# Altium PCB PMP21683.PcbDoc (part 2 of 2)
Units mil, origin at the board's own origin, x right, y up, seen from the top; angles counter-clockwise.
Board outline 4950 x 3450 mil, 2 copper layers (Top Layer, Bottom Layer), stack 62 mil thick; 134 components, 57 nets, 365 pads, 111 vias.
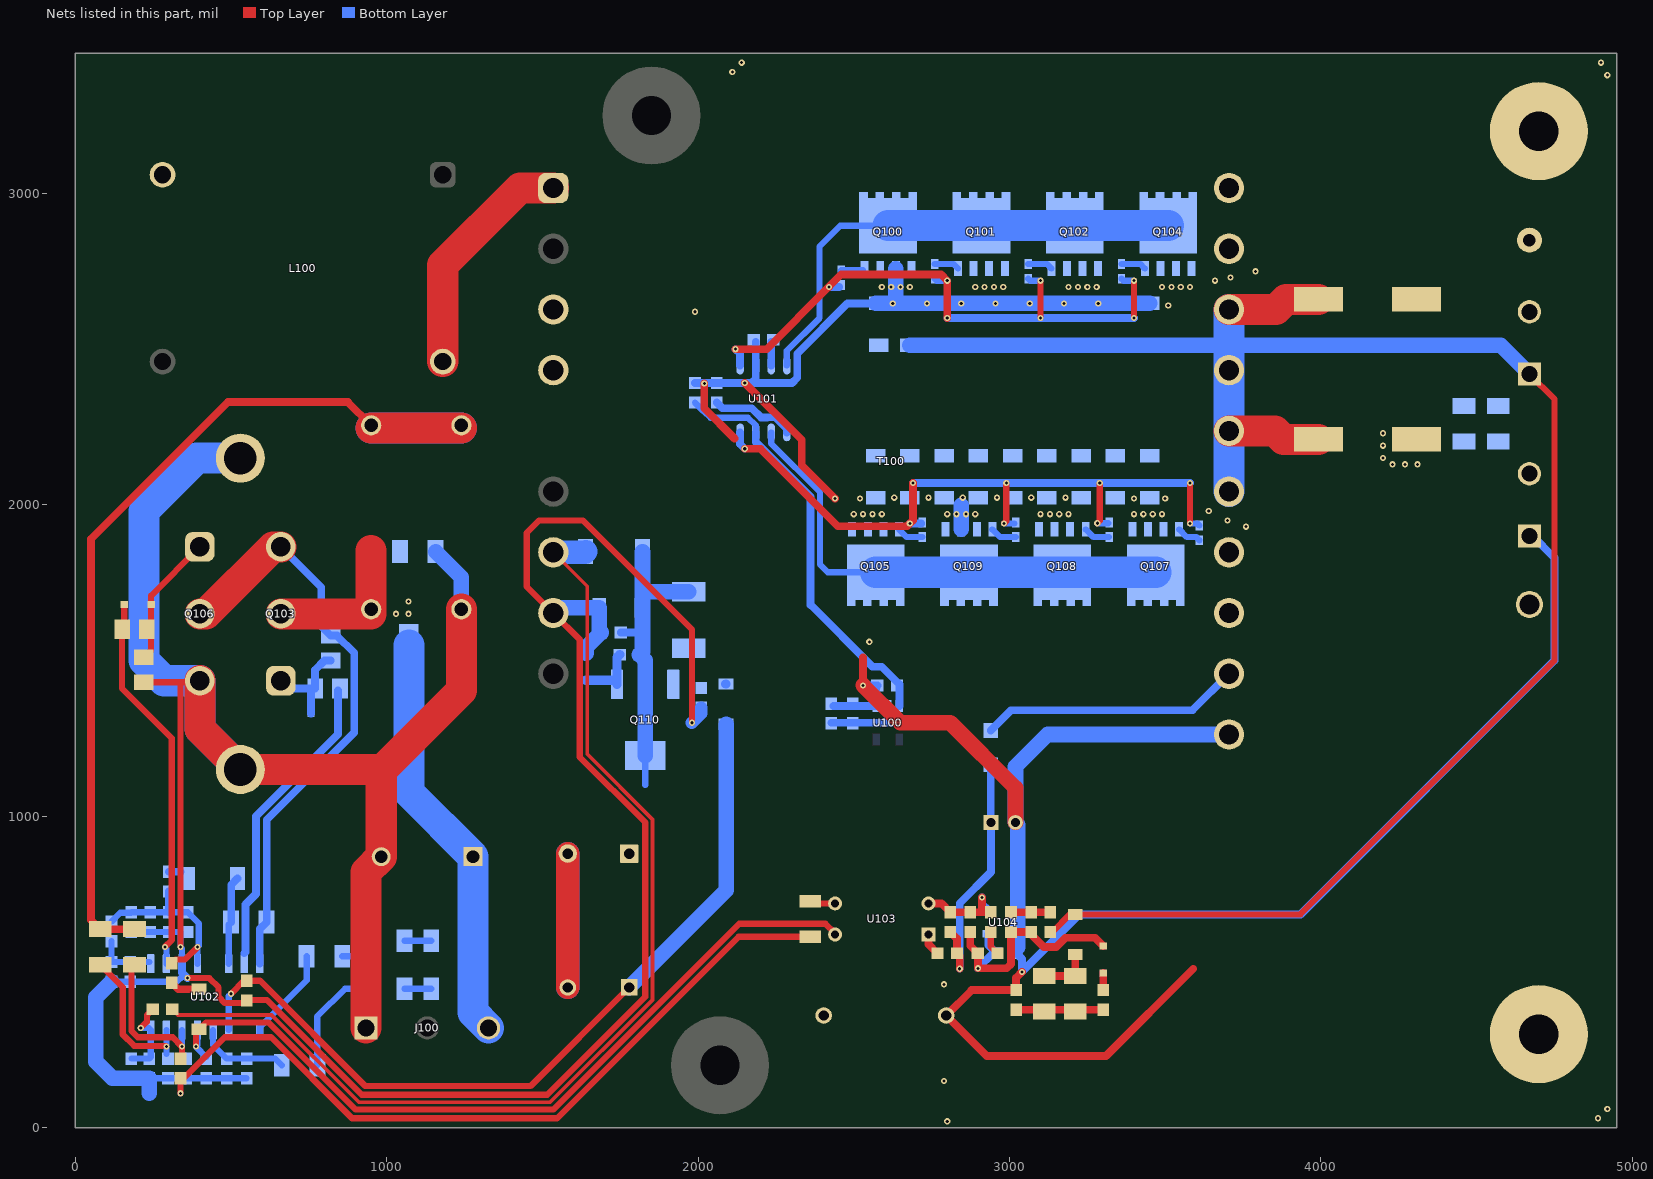
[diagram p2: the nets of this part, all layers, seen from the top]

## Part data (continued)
R136: "RES, 412 k, 1%, 0.1 W, 0603", MANUFACTURER=Vishay-Dale, Power_W=0.1, Supplier Part Number 1=541-412KHCT-ND, TempCo="100 ppm/C", Tolerance_%=1, Value1=1%, Value2=0.1W, Value_Code=412k
R137: "RES, 68.1, 1%, 0.1 W, 0603", MANUFACTURER=Vishay-Dale, Power_W=0.1, Supplier Part Number 1=541-68.1HCT-ND, TempCo="100 ppm/C", Tolerance_%=1, Value1=1%, Value2=0.1W, Value_Code=68R1, ValueDisplayed=68.1
R138: "RES, 57.6 k, 1%, 0.1 W, 0603", MANUFACTURER=Vishay-Dale, Power_W=0.1, Supplier Part Number 1=541-57.6KHCT-ND, TempCo="100 ppm/C", Tolerance_%=1, Value1=1%, Value2=0.1W, Value_Code=57k6, ValueDisplayed=57.6k
T100: library part CMP-0084748-1, "Transformer, 250 uH, TH", MANUFACTURER="Renco Electronics", ValueDisplayed=250µH
TP100: "Test Point, Miniature, Red, TH", Color=Red, MANUFACTURER=Keystone, Supplier Part Number 1=36-5000-ND
TP101: "Test Point, Multipurpose, Black, TH", Color=Black, MANUFACTURER=Keystone, Supplier Part Number 1=36-5011-ND
U100: library part CMP-0035558-1, "Single Output LDO, 150 mA, Fixed 5 V Output, 2.5 to 24 V Input, with Ultra-Low IQ, 5-pin SOT-23 (DBV), -40 to 125 degC, Green (RoHS & no Sb/Br)", MANUFACTURER="Texas Instruments"
U101: library part CMP-0079610-1, "High Performance Synchronous Rectifier Driver for LLC Resonant Converter, D0008A (SOIC-8)", Alternate Manufacturer="Texas Instruments"
U102: library part UCC25630DDB, "Enhanced LLC Resonant Controller with Driver, DDB0014A", Alternate Manufacturer="Texas Instruments"
U103: library part VO618A, "OPTOISOLATOR 5.3KV TRANS 4-DIP", MANUFACTURER=Vishay-Semiconductor, Voltage_Isolation_Vrms=5300V
U104: "Low-Voltage Adjustable Precision Shunt Regulator, 80 mA, -40 to 125 degC, 3-pin SOT-23 (DBZ), Green (RoHS & no Sb/Br)", Alternate Manufacturer="Texas Instruments", Alternate PartNumber=Equivalent, Rating=Catalog, Supplier Part Number 1=296-17972-2-ND, Temp Coeff(Max)(ppm/ degree C)=129

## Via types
v1: diameter 20, hole 10, Top Layer to Bottom Layer, 111 vias

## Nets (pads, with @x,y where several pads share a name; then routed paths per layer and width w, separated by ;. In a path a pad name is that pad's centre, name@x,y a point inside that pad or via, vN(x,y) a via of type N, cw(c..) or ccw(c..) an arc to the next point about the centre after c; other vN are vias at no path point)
5Vs: C106.1 C135.1 U100.3 U101.7 | length 1334.9
  Bottom Layer w20: C135.1@1990,2328.5 2017.13,2301.38 2018.62,2301.38 2040,2280 2160,2280 2185,2255 U101.7@2185,2232.72
  Bottom Layer w25: U101.7@2185,2232.72 2185,2202.04 2361.38,2025.67 2361.38,1678.62 2560,1480 2590,1480 2646.46,1423.54 U100.3@2646.46,1354.29
BLK: C154.1 R129.1 R138.2 U102.4 | length 296
  Bottom Layer w20: U102.4@442.5,313.7 442.5,265.04 C154.1@486.04,221.5 R138.2@550,221.5 641.42,221.5 R129.1@662.91,200
FB: C145.1 D107.2 U102.5 U103.4 | length 2594.1
  Top Layer w20: v1(387.5,260) 387.5,305.53 D107.2@397.5,315.53 419.84,337.87 620,337.87 900,57.87 1535.4,57.87 2132.24,654.71 2408.75,654.71 2440,623.46 U103.4@2440,620
  Bottom Layer w20: U102.5@392.5,313.7 392.5,265 v1(387.5,260) C145.1@420.93,226.57
GND: C100.2 C102.2 C103.2 C107.2 C131.2 C132.1 C133.2 C141.2 C142.2 C143.1 C144.1 C145.2 C146.2 C147.2 C148.2 C149.2 C150.2 C151.2 C152.2 C153.2 C154.2 D109.2 H100.1 H100.2 J100.1 Q106.3 R112.1 R113.1 R135.1 R136.1 R137.1 R138.1 T100.8 U102.11 | length 14543.6
  Top Layer w20: R113.1@220,1430 340,1430 ; v1(337.5,110) R137.1@337.5,158.5 348.5,158.5 480,290 628.45,290 888.45,30 1546.95,30 2130.06,613.11 R135.1@2360,613.11 ; v1(337.5,580) 337.5,1427.5 340,1430 ; v1(360,480) 360.35,480.35 428.92,480.35 429.27,480 430,480 460,450 460,420 480,400 541.5,400 C144.1@550,408.5 551.5,410 615.4,410 919.78,105.62 1515.62,105.62 1830,420 1830,980 1620,1190 1620,1567.5 T100.8@1535,1652.5 1450,1737.5 1450,1910 1490,1950 1630,1950 1980,1600 v1(1980,1300) ; Q106.3@395,1430 340,1430
  Top Layer w75: C141.2@1581.57,450 C142.2@1581.57,880
  Top Layer w100: Q106.3@400,1435 400,1280 H100.2@530,1150 986.54,1150 1240,1403.46 C131.2@1240,1664.72 ; J100.1@933.15,320 933.15,820.79 C100.2@982.36,870 982.36,1145.83
  Bottom Layer w20: R136.1@116.04,468.5 C151.2@176.04,468.5 ; C151.2@177.5,467.05 C151.2@176.04,468.5 ; C147.2@180,628.5 C148.2@240,628.5 C150.2@300,628.5 337.5,628.5 v1(337.5,580) 342.5,575 U102.11@342.5,526.3 ; C153.2@237.5,158.5 C152.2@297.5,158.5 C146.2@356.18,158.5 C145.2@420.93,158.5 C154.2@486.04,158.5 R138.1@550,158.5 ; U102.11@342.5,497.5 342.5,485 326,468.5 C151.2@176.04,468.5
  Bottom Layer w25: U102.11@342.5,526.3 342.5,497.5 v1(360,480)
  Bottom Layer w39.37: v1(1980,1300) 2010,1330 C143.1@2010,1348.5
  Bottom Layer w50: R136.1@116.04,468.5 65.96,418.43 65.96,211.54 119,158.5 C153.2@237.5,158.5 237.5,110 ; C102.2@1157.09,1850 1240,1767.09 C131.2@1240,1664.72 1228.74,1653.46 C103.2@1228.74,1550 ; T100.8@1552.5,1670 C133.2@1683.07,1670 1683.07,1595.43 C132.1@1688.5,1590 1640,1541.5 D109.2@1640,1523.31
  Bottom Layer w75: C141.2@1581.57,450 C142.2@1581.57,880
  Bottom Layer w100: H100.2@530,1150 400,1280 Q106.3@400,1435 285,1435 220,1500 220,1980 390,2150 H100.1@530,2150
HO: D101.1 R105.1 U102.15 | length 967.9
  Bottom Layer w25: 542.5,560 546.38,563.88 546.38,716.38 580,750 580,1000.12 843.31,1263.42 D101.1@843.31,1330 R105.1@843.31,1403.31
HS: C136.2 L100.2 Q103.3 Q106.2 R104.1 U102.16 | length 1922.4
  Top Layer w100: Q106.2@400,1650 420,1650 635,1865 Q103.3@660,1865
  Bottom Layer w25: U102.16@592.5,526.3 592.5,637.91 C136.2@614.59,660 614.59,988.21 895.37,1269 895.37,1524.63 840,1580 R104.1@820,1580 790,1610 790,1735 Q103.3@660,1865
ISNS: C129.2 C146.1 R137.2 U102.6 | length 506.5
  Top Layer w20: C129.2@180,512.91 180,310.58 200.58,290 312.5,290 v1(342.5,260) R137.2@342.5,226.5
  Bottom Layer w20: C146.1@342.5,226.5 v1(342.5,260) U102.6@342.5,313.7
LO: D103.1 R114.1 U102.10 | length 1233.8
  Top Layer w20: D103.1@156.69,1680 156.69,1606.69 R114.1@150,1600 150,1410 309.63,1250.37 309.63,602.13 v1(287.5,580)
  Bottom Layer w20: v1(287.5,580) 292.5,575 U102.10@292.5,526.3
NetC108_2: C108.2 C129.1 C130.1 C131.1 T100.3 T100.4 | length 3068.5
  Top Layer w25: C129.1@190,637.09 C130.1@80,637.09 50,667.09 50,1890 490,2330 875.28,2330 C108.2@950,2255.28
  Top Layer w100: C108.2@950,2246.85 C131.1@1240,2246.85
  Bottom Layer w100: C108.2@950,2246.85 C131.1@1240,2246.85
NetC134_2: C134.2 U101.3 | length 76.2
  Bottom Layer w25: U101.3@2235,2447.28 C134.2@2235,2523.5
NetC136_1: C136.1 D104.1 U102.14 | length 274
  Bottom Layer w20: U102.14@492.5,526.3 C136.1@492.5,652.09
  Bottom Layer w25: C136.1@500.41,660 500.41,780.1 D104.1@520.32,800
NetC137_1: C137.1 C139.2 R127.1 U103.2 U104.2 | length 308.8
  Top Layer w25: U103.2@2740,720 2781.5,720 R127.1@2810,691.5 C137.1@2874.21,691.5 2911.46,691.5 ; v1(2911.46,738.54) 2911.46,691.5 ; C139.2@2940,691.5 2911.46,691.5
  Bottom Layer w25: v1(2911.46,738.54) 2911.46,718.7 U104.2@2932.76,697.4
NetC137_2: C137.2 C138.1 D108.1 R128.1 R131.2 R139.2 U104.1 | length 829.4
  Top Layer w25: C137.2@2874.21,628.5 2874.21,584.29 R131.2@2898.5,560 v1(2898.5,511.5) 2991.5,511.5 3005,525 R128.1@3005,628.5 C138.1@3070,628.5 3070,620 3110,580 3150,580 3180,610 3274.61,610 D108.1@3301.3,583.31
  Bottom Layer w25: v1(2898.5,511.5) R139.2@2947.01,560 ; U104.1@2932.76,622.6 2932.76,585.73 R139.2@2958.49,560
NetC138_2: C138.2 R118.2 R128.2 | length 126.3
  Top Layer w25: R128.2@3005,691.5 C138.2@3070,691.5 R118.2@3131.3,691.5
NetC139_1: C139.1 R131.1 | length 77.4
  Top Layer w20: C139.1@2940,628.5 2940,581.5 R131.1@2961.5,560
NetC140_1: C140.1 D105.2 R132.2 | length 168.4
  Top Layer w25: C140.1@3111.3,487.09 R132.2@3211.3,487.09 D105.2@3211.3,555.53
NetC140_2: C140.2 R132.1 R134.2 R140.2 | length 280
  Top Layer w25: R140.2@3021.3,378.5 R134.2@3301.3,378.5
NetC141_1: C141.1 C144.2 D106.1 U102.3 | length 2652.2
  Top Layer w20: v1(500,430) C144.2@541.5,471.5 ; C144.2@550,471.5 593.32,471.5 931.32,133.5 1461.92,133.5 C141.1@1778.43,450
  Bottom Layer w20: U102.3@492.5,313.7 492.5,422.5 v1(500,430)
  Bottom Layer w50: C141.1@1778.43,450 2090,761.57 D106.1@2090,1295.53
NetC143_2: C143.2 D106.2 Q110.3 R120.2 | length 1.1
  Bottom Layer w29.53: D106.2@2088.9,1424.47 D106.2@2090,1424.47
NetC151_1: C151.1 R133.1 R136.2 U102.9 | length 188.3
  Bottom Layer w20: R133.1@116.04,598.5 R136.2@116.04,531.5 U102.9@237.3,531.5
NetD101_2: D101.2 Q103.1 R104.2 R105.2 | length 309.5
  Bottom Layer w25: Q103.1@660,1435 685,1410 R105.2@770,1410 770,1470 800,1500 R104.2@820,1500 ; D101.2@756.69,1330 R105.2@756.69,1396.69
NetD102_2: D102.2 R110.2 T100.7 | length 3476.1
  Top Layer w12: R110.2@311.5,380 329.75,361.75 629.89,361.75 909.89,81.75 1525.51,81.75 1853.87,410.11 1853.87,989.89 1643.87,1199.89 1643.87,1738.63 T100.7@1535,1847.5
  Bottom Layer w75: T100.7@1535,1847.5 1636.16,1847.5 D102.2@1638.66,1850
NetD103_2: D103.2 Q106.1 R113.2 R114.2 | length 429.6
  Top Layer w20: R113.2@220,1510 243.31,1533.31 D103.2@243.31,1680 243.31,1708.31 Q106.1@400,1865
NetD104_2: D104.2 R117.2 | length 38.2
  Bottom Layer w25: R117.2@300,821.5 D104.2@338.19,821.5
NetD107_1: D107.1 R121.1 | length 96.1
  Top Layer w25: R121.1@310,465.21 330.74,444.47 D107.1@397.5,444.47
NetD108_2: D108.2 R134.1 | length 55.2
  Top Layer w25: R134.1@3301.3,441.5 D108.2@3301.3,496.69
NetD109_1: D109.1 Q110.1 R130.1 | length 195.4
  Bottom Layer w29.53: D109.1@1640,1436.69 Q110.1@1736.14,1436.69 ; Q110.1@1739.45,1423.36 1739.45,1509.84 R130.1@1748.49,1518.88
NetL100_4: L100.4 T100.1 | length 767.5
  Top Layer w100: L100.4@1180,2460 1180,2770 1427.5,3017.5 T100.1@1535,3017.5
NetQ100_4: Q100.4 R100.1 | length 69.8
  Bottom Layer w20: R100.1@2460,2753.62 Q100.4@2529.84,2753.62
NetQ101_4: Q101.4 R101.1 | length 81.1
  Bottom Layer w20: R101.1@2760,2773.62 2820.16,2773.62 Q101.4@2835,2758.78
NetQ102_4: Q102.4 R102.1 | length 81.1
  Bottom Layer w20: R102.1@3060,2773.62 3120.16,2773.62 Q102.4@3135,2758.78
NetQ104_4: Q104.4 R103.1 | length 81.1
  Bottom Layer w20: R103.1@3360,2773.62 3420.16,2773.62 Q104.4@3435,2758.78
NetQ105_4: Q105.4 R108.1 | length 85.3
  Bottom Layer w20: Q105.4@2645,1921.22 2669.84,1896.38 R108.1@2720,1896.38
NetQ107_4: Q107.4 R109.1 | length 79.4
  Bottom Layer w20: Q107.4@3545,1921.22 3569.84,1896.38 3600,1896.38 R109.1@3610,1886.38
NetQ108_4: Q108.4 R111.1 | length 85.3
  Bottom Layer w20: Q108.4@3245,1921.22 3269.84,1896.38 R111.1@3320,1896.38
NetQ109_4: Q109.4 R115.1 | length 85.3
  Bottom Layer w20: Q109.4@2945,1921.22 2969.84,1896.38 R115.1@3020,1896.38
NetR116_1: R116.1 U101.5 | length 272.5
  Bottom Layer w25: R116.1@2060,2328.5 2078.13,2310.37 2172.58,2310.37 2202.05,2280.9 2220.94,2280.9 2221.67,2281.63 2248.33,2281.63 2285,2244.97 U101.5@2285,2232.72
NetR119_1: R119.1 R126.2 | length 85.8
  Bottom Layer w20: R126.2@1057.09,446.26 R119.1@1142.91,446.26
NetR122_1: R122.1 U103.1 | length 71.8
  Top Layer w25: U103.1@2740,620 2740,588.5 R122.1@2768.5,560
NetR123_1: R123.1 R124.2 | length 85.8
  Bottom Layer w20: R124.2@1057.09,600 R123.1@1142.91,600
NetR124_1: R124.1 R125.2 | length 99.5
  Bottom Layer w20: R125.2@857.09,550 910,550 R124.1@942.91,582.91
NetR125_1: R125.1 U102.1 | length 317.3
  Bottom Layer w20: U102.1@592.5,295 U102.1@592.5,313.7 592.5,322.5 742.91,472.91 R125.1@742.91,550
NetR126_1: R126.1 R129.2 | length 359.9
  Bottom Layer w20: R129.2@777.09,200 777.09,357.09 866.26,446.26 R126.1@942.91,446.26
NetR135_2: R135.2 U103.3 | length 73.1
  Top Layer w20: R135.2@2366.89,720 U103.3@2440,720
OV: C153.1 R110.1 R112.2 U102.8 | length 253.9
  Top Layer w20: v1(210,320) 230,340 230,361.5 R110.1@248.5,380
  Bottom Layer w20: R112.2@180,221.5 C153.1@237.5,221.5 242.5,226.5 U102.8@242.5,313.7 ; v1(210,320) U102.8@236.2,320
RVCC: C147.1 C148.1 C149.1 C150.1 R117.1 R121.2 R133.2 U102.12 | length 609.8
  Top Layer w20: R121.2@310,528.2 321.8,540 352.5,540 v1(392.5,580)
  Bottom Layer w20: R133.2@116.04,661.5 144.53,689.98 178.49,689.98 C147.1@180,691.5 C148.1@240,691.5 C150.1@300,691.5 C149.1@360,691.5 360.67,691.5 396.57,655.59 396.57,584.07 v1(392.5,580) U102.12@392.5,526.3
  Bottom Layer w25: C150.1@300,691.5 R117.1@300,758.5
SGND: C101.2 C104.1 C105.1 C106.2 C107.1 C109.2 C110.2 C111.2 C112.2 C113.2 C114.2 C115.2 C116.2 C117.2 C118.2 C119.1 C120.1 C121.1 C122.1 C123.1 C124.1 C125.1 C126.1 C127.1 C128.1 C134.1 C135.2 H101.1 H106.1 J102.1 J102.2 Q100.1 Q100.2 Q100.3 Q101.1 Q101.2 Q101.3 Q102.1 Q102.2 Q102.3 Q104.1 Q104.2 Q104.3 Q105.1 Q105.2 Q105.3 Q107.1 Q107.2 Q107.3 Q108.1 Q108.2 Q108.3 Q109.1 Q109.2 Q109.3 R106.2 R107.2 R116.2 R139.1 R140.1 T100.11 TP101.1 U100.1 U101.2 U104.3 | length 8963.9
  Top Layer w25: v1(2020,2390) 2020,2310 2117.13,2212.87 ; v1(2150,2391.5) 2332.87,2208.62 2332.87,2127.13 v1(2440,2020) ; v1(2530,1420) 2530,1510 ; v1(3040,500) 3021.3,481.3 R140.1@3021.3,441.5 2878.35,441.5 C107.1@2796.85,360 2926.85,230 3310,230 3590,510
  Top Layer w50: v1(2530,1420) 2649.84,1300.16 2809.84,1300.16 3019.37,1090.63 C101.2@3019.37,980
  Bottom Layer w25: C135.2@1990,2391.5 R116.2@2060,2391.5 v1(2150,2391.5) 2171.5,2391.5 ; C134.1@2185,2523.5 U101.2@2185,2447.28 2185,2405 2171.5,2391.5 ; C105.1@2434.41,1354.29 U100.1@2571.65,1354.29 C106.2@2571.65,1415.94 ; v1(2530,1420) C106.2@2575.71,1420 ; C119.1@2570,2646.93 2479.88,2646.93 2318.27,2485.31 2318.27,2408.27 2301.5,2391.5 2171.5,2391.5 ; 3027.24,580 3027.24,565.77 R139.1@3021.48,560 3040,541.48 v1(3040,500) 3224.47,684.47 3934.47,684.47 4750,1500 4750,1830 4680,1900 J102.1@4670,1900
  Bottom Layer w50: C119.1@2570,2646.93 v1(2625,2646.93) C110.2@2680,2646.93 C113.2@2790,2646.93 C116.2@2900,2646.93 C115.2@3010,2646.93 C120.1@3120,2646.93 C111.2@3230,2646.93 C112.2@3340,2646.93 C114.2@3450,2646.93 ; 2635,2651.93 Q100.2@2635,2758.78 ; Q109.2@2845,1921.22 2845,1998.07 ; 3027.24,580 U104.3@3027.24,660 3027.24,972.13 C101.2@3019.37,980 3019.37,1159.37 3122.5,1262.5 T100.11@3705,1262.5
  other v1: 2800,20 4890,30 4920,60 2790,150 2790,460 2550,1560 3760,1930 3700,1950 2500,1970 2530,1970 2560,1970 2590,1970 2800,1970 2830,1970 2860,1970 2890,1970 3100,1970 3130,1970 3160,1970 3190,1970 3400,1970 3430,1970 3460,1970 3490,1970 3640,1980 2520,2020 3400,2020 3500,2020 2630,2023.07 2740,2023.07 2850,2023.07 2960,2023.07 3070,2023.07 3180,2023.07 4230,2130 4270,2130 4310,2130 4200,2150 4200,2190 4200,2230 1990,2620 3510,2640 2735,2646.93 2845,2646.93 2955,2646.93 3065,2646.93 3175,2646.93 3285,2646.93 2590,2700 2620,2700 2650,2700 2680,2700 2890,2700 2920,2700 2950,2700 2980,2700 3190,2700 3220,2700 3250,2700 3280,2700 3490,2700 3520,2700 3550,2700 3580,2700 3660,2720 3710,2730 3790,2750 4920,3380 2110,3390 2140,3420 4900,3420
Vb: D100.2 T100.12 | length 840.5
  Bottom Layer w25: D100.2@2940,1275.12 3004.88,1340 3587.5,1340 T100.12@3705,1457.5
Vb1: C101.1 C104.2 C105.2 D100.1 R122.2 R127.2 U100.2 | length 1453.1
  Top Layer w25: R127.2@2810,628.5 2831.5,607.01 R122.2@2831.5,560 2840,551.5 v1(2840,510)
  Bottom Layer w25: C105.2@2428.86,1300.16 2599.21,1300.16 ; U100.2@2609.05,1354.29 2609.05,1310 2599.21,1300.16 ; v1@2840.63,510.63 v1(2840,510) 2840,720 2940.63,820.63 C101.1@2940.63,980 ; C101.1@2940,980.63 D100.1@2940,1164.88 2804.72,1300.16 2599.21,1300.16
VCC: C132.2 C133.1 C142.1 D102.1 Q110.2 Q110.4 R120.1 R130.2 | length 969.7
  Bottom Layer w20: 1830,1100 Q110.4@1830,1195.02
  Bottom Layer w25: C132.2@1751.5,1590 1811.34,1590
  Bottom Layer w50: D102.1@1821.34,1850 1821.34,1528.74 R130.2@1811.48,1518.88 1830,1500.35 Q110.2@1830,1423.36 Q110.4@1830,1195.02 ; 1821.89,1720.55 R120.1@1970,1720.55
VCR: C130.2 C152.1 U102.7 | length 487.5
  Top Layer w20: C130.2@80,522.91 152.13,450.79 152.13,299.03 189.03,262.13 290.37,262.13 v1(292.5,260)
  Bottom Layer w20: C152.1@292.5,236.5 v1(292.5,260) U102.7@292.5,313.7
VD_SR1: Q100.5 Q100.6 Q100.7 Q100.8 Q100.9 Q101.5 Q101.6 Q101.7 Q101.8 Q101.9 Q102.5 Q102.6 Q102.7 Q102.8 Q102.9 Q104.5 Q104.6 Q104.7 Q104.8 Q104.9 T100.19 T100.20 U101.4 | length 1574.1
  Bottom Layer w20: U101.4@2285,2447.28 2285,2495 2390,2600 2390,2687.04 2389.63,2687.42 2389.63,2712.96 2390,2713.33 2390,2830 2456.57,2896.57 Q100.9@2610,2896.57
  Bottom Layer w100: Q100.9@2610,2896.57 Q101.9@2910,2896.57 Q102.9@3210,2896.57 Q104.9@3510,2896.57
VD_SR2: Q105.5 Q105.6 Q105.7 Q105.8 Q105.9 Q107.5 Q107.6 Q107.7 Q107.8 Q107.9 Q108.5 Q108.6 Q108.7 Q108.8 Q108.9 Q109.5 Q109.6 Q109.7 Q109.8 Q109.9 T100.13 T100.14 U101.6 | length 1577.9
  Bottom Layer w20: U101.6@2235,2232.72 2235,2196.75 2391.75,2040 2391.75,1808.25 2416.57,1783.43 Q105.9@2570,1783.43
  Bottom Layer w100: Q105.9@2570,1783.43 Q109.9@2870,1783.43 Q108.9@3170,1783.43 Q107.9@3470,1783.43
VG_SR1: R100.2 R101.2 R102.2 R103.2 U101.1 | length 1968.2
  Top Layer w20: v1(3100,2600) v1(3100,2720) ; v1(3400,2600) v1(3400,2720)
  Top Layer w25: v1(2120,2500) 2220,2500 v1(2420,2700) 2460,2740 2780,2740 v1(2800,2720) v1(2800,2600)
  Bottom Layer w20: R101.2@2760,2726.38 2766.38,2720 v1(2800,2720) ; R102.2@3060,2726.38 3066.38,2720 v1(3100,2720) ; R103.2@3360,2726.38 3366.38,2720 v1(3400,2720)
  Bottom Layer w25: v1(2120,2500) 2135,2485 U101.1@2135,2447.28 ; v1(2420,2700) R100.2@2453.62,2700 ; v1(2800,2600) v1(3100,2600) v1(3400,2600)
VG_SR2: R108.2 R109.2 R111.2 R115.2 U101.8 | length 2253.5
  Top Layer w20: v1(2982.49,1940) 2990,1947.51 v1(2990,2070) ; v1(3282.17,1940.77) 3290,1948.6 v1(3290,2070) ; v1(3580,1939.74) v1(3580,2070)
  Top Layer w25: v1(2150,2180) 2200,2180 2448.94,1931.06 2671.06,1931.06 v1(2680,1940) 2690,1950 v1(2690,2070)
  Bottom Layer w20: v1(2982.49,1940) R115.2@3016.38,1940 ; v1(3282.17,1940.77) R111.2@3317.15,1940.77 ; v1(3580,1939.74) 3603.88,1939.74 R109.2@3610,1933.62
  Bottom Layer w25: U101.8@2135,2232.72 2135,2195 v1(2150,2180) ; v1(2680,1940) R108.2@2716.38,1940 ; v1(2690,2070) v1(2990,2070) v1(3290,2070) v1(3580,2070)
VIN: C100.1 C102.1 C103.1 C108.1 J100.3 Q103.2 R119.2 R123.2 | length 1829
  Top Layer w100: Q103.2@660,1650 950,1650 950,1853.15
  Bottom Layer w100: C103.1@1071.26,1550 1071.26,1076.38 C100.1@1277.64,870 1277.64,369.21 J100.3@1326.85,320
  other v1: 1030,1650 1070,1650 1070,1690
Vout: C109.1 C110.1 C111.1 C112.1 C113.1 C114.1 C115.1 C116.1 C117.1 C118.1 C119.2 C120.2 C121.2 C122.2 C123.2 C124.2 C125.2 C126.2 C127.2 C128.2 D105.1 J101.1 J101.2 R106.1 R107.1 R118.1 T100.15 T100.16 T100.17 T100.18 TP100.1 | length 6146.3
  Top Layer w20: R118.1@3131.3,628.5 3138.5,628.5 3194.47,684.47 D105.1@3211.3,684.47 3934.47,684.47 4750,1500 4750,2340 J101.1@4670,2420
  Top Layer w100: T100.16@3705,2237.5 3852.5,2237.5 3880,2210 C109.1@3992.52,2210 ; T100.18@3705,2627.5 3855.85,2627.5 3888.35,2660 C118.1@3992.52,2660
  Bottom Layer w50: C110.1@2680,2513.07 C113.1@2790,2513.07 C116.1@2900,2513.07 C115.1@3010,2513.07 C120.2@3120,2513.07 C111.1@3230,2513.07 C112.1@3340,2513.07 C114.1@3450,2513.07 3705,2513.07 4576.93,2513.07 J101.1@4670,2420
  Bottom Layer w100: T100.15@3705,2042.5 T100.16@3705,2237.5 T100.17@3705,2432.5 3705,2513.07 T100.18@3705,2627.5
pads on no net: H107.1 H108.1 J100.2 L100.1 L100.3 T100.2 T100.6 T100.9 U100.4 U100.5

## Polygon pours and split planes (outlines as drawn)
GND on Top Layer "GND" (solid, pour order 36): 200,1460 191.46,1451.46 191.46,1421.46 190,1420 330,1280 337.5,1280 337.5,1370 360,1370 360,740 910,190 1030,190 1080,240 1080,280 1490,690 1490,1220 1430,1280 1430,1677.8 1377.8,1730 1200,1730 1180,1710 1180,1630 1090,1540 930,1540 725.32,1335.32 604.68,1335.32 450,1490 370,1490 340,1460
SGND on Top Layer "SGND" (solid, pour order 32): 2110,3440 2090,3420 2090,2750 1970,2630 1970,2020 2490,1500 2520,1500 2520,3440
NetC108_2 on Top Layer "C108_2" (solid, pour order 8): 920,2310 900,2290 900,2150 920,2130 1320,2130 1590,2400 1590,2660 1570,2680 1490,2680 1330,2520 1330,2450 1190,2310
NetL100_4 on Top Layer "L100_4" (solid, pour order 6): 1120,2410 1100,2430 1100,2840 1340,3080 1580,3080 1600,3060 1600,2940 1580,2920 1440,2920 1270,2750 1270,2470 1210,2410
VIN on Top Layer "Vin" (solid, pour order 2): 630,1700 610,1680 610,1620 630,1600 1070,1600 1130,1660 1130,1852.05 1072.05,1910 830,1910 810,1890 810,1840 670,1700
SGND on Top Layer "SGND" (solid, pour order 28): 4920,10 4940,30 4940,3420 4920,3440 2500,3440 2480,3420 2480,1290 2770,1000 2770,30 2790,10
GND on Bottom Layer "GND" (solid, pour order 50): 110,2240 10,2140 10,1170 110,1070 560,1070 610,1120 610,1300 420,1490 310,1490 280,1520 280,1950 400,2070 570,2070 610,2110 610,2180 550,2240
GND on Bottom Layer "GND" (solid, pour order 42): 970,220 1690,220 1690,10 980,10 960,30
GND on Bottom Layer "GND" (solid, pour order 38): 390,630 410,610 410,470 440,440 511.46,440 521.46,430 521.46,228.54 610,140 820,140 850,170 850,330 880,360 980,360 1140,200 1140,20 1130,10 30,10 10,30 10,630
SGND on Bottom Layer "SGND" (solid, pour order 34): 2408.5,1310 2410,1311.5 2410,1460 2500,1550 2500,1831.32 1970,2361.32 1970,2630 2090,2750 2090,3420 2110,3440 2540,3440 2540,1320 2530,1310
HS on Bottom Layer "HS" (solid, pour order 4): 370,1590 340,1620 340,1680 499.09,1839.09 499.09,1939.09 630,2070 630,2870 560,2940 250,2940 230,2960 230,3110 250,3130 670,3130 830,2970 830,1960 460,1590
NetC143_2 on Bottom Layer "C141_2" (solid, pour order 16): 1920,1580 1900,1560 1900,1540 1900,1470 1900,1400 1910,1390 2110,1390 2130,1410 2130,1500 2050,1580
VCC on Bottom Layer "VCC" (solid, pour order 14): 1760,840 1750,850 1750,1339.87 1780.13,1370 1780,1550 1770,1560 1740,1560 1740,1561.3 1730,1571.3 1730,1620 1770,1660 1770,1890 1790,1910 1871.89,1910 2040,1741.89 2040,1680 2020,1660 1960,1660 1880,1580 1880,1350 1910,1320 1910,930 1820,840
VIN on Bottom Layer "Vin" (solid, pour order 12): 920,1910 890,1880 890,1683.46 1043.46,1530 1100,1530 1120,1550 1120,1760 1080,1800 1080,1890 1060,1910
NetL100_4 on Bottom Layer "L100_4" (solid, pour order 10): 1120,2410 1100,2430 1100,2840 1340,3080 1580,3080 1600,3060 1600,2940 1580,2920 1440,2920 1270,2750 1270,2470 1210,2410
Vout on Bottom Layer "Vout" (solid, pour order 18): 2530,2530 2530,2138.91 2578.91,2090 3590,2090 3690,1990 3890,1990 4180,2280 4710,2280 4730,2300 4730,2890 4710,2910 4055,2910 3825,2680 3674.79,2680 3574.79,2580 2580,2580
VD_SR1 on Bottom Layer "VD_SR1" (solid, pour order 20): 2470,2800 2450,2820 2450,3000 2550,3100 3750,3100 3770,3080 3770,2800 3740,2770 3680,2770 3650,2800
SGND on Bottom Layer "SGND" (solid, pour order 22): 2570,2620 2560,2630 2560,2780 2570,2790 3600,2790 3610,2780 3610,2680 3550,2620
VD_SR2 on Bottom Layer "VD_SR2" (solid, pour order 24): 3770,1880.16 3750.16,1900 3658.5,1900 3630.5,1872 2432,1872 2410,1850 2410,1660 2470,1600 3750,1600 3770,1620
SGND on Bottom Layer "SGND" (solid, pour order 26): 2430,1890 2410,1910 2410,2030 2430,2050 3500,2050 3520,2030 3520,1900 3510,1890
SGND on Bottom Layer "SGND" (solid, pour order 30): 4920,10 4940,30 4940,3420 4920,3440 2500,3440 2480,3420 2480,1290 2770,1000 2770,30 2790,10
GND on Bottom Layer "GND" (solid, pour order 44): 1490,1710 1420,1640 1420,270 1370,220 990,220 970,200 970,30 990,10 2410,10 2430,30 2430,410 2130,710 2130,1197.95 1617.95,1710
GND on Bottom Layer "GND" (solid, pour order 46): 1150,1910 1130,1890 1130,1810 1190,1750 1190,1480 1210,1460 1290,1460 1310,1480 1310,1840 1240,1910
NetC108_2 on Bottom Layer "C108_2" (solid, pour order 48): 920,2310 900,2290 900,2150 920,2130 1320,2130 1590,2400 1590,2660 1570,2680 1490,2680 1330,2520 1330,2450 1190,2310

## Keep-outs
Keep-Out Layer:
  text ".Layer_Name" at 577,-858.49 h60

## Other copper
Top Layer:
  text ".Layer_Name" at 577,-858.49 h60
Bottom Layer:
  text ".Layer_Name" at 577,-858.49 h60

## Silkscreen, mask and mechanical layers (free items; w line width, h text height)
Top Overlay:
  region: 4480,400 4180,400 4180,300 4480,300
  lines w10: 80,1530 80,1570 100,1590 ; 910,80 950,80 ; 1310,80 1350,80 ; 1330,60 1330,100 ; 2780,520 2780,510 2800,490 ; 4880,2690 4920,2690 ; 4900,1830 4900,1870 ; 4900,2670 4900,2710
  text "'.PRJ_Number'.PCB_Rev-" at 3590,310 h108.27
  text "400VDC Norminal" at 50,30 h60
  text ".Layer_Name" at 577,-858.49 h60
Bottom Overlay:
  lines w10: 110,880 110,750 130,730 ; 1580,1570 1600,1590 1640,1590 ; 1850,1560 1860,1570 1860,1590 ; 30,910 60,880 140,880 350,1090 350,1210 330,1230 80,1230 30,1180 30,910
  text ".Layer_Name" at 577,-858.49 h60
Top Paste:
  text ".Layer_Name" at 577,-858.49 h60
Bottom Paste:
  text ".Layer_Name" at 577,-858.49 h60
Top Solder:
  text ".Layer_Name" at 577,-858.49 h60
  text ".Layer_Name" at 577,-858.49 h60
Bottom Solder:
  text ".Layer_Name" at 577,-858.49 h60
Drill Guide:
  text ".Layer_Name" at 577,-858.49 h60
M1 Board Outline:
  the board outline again, w10
  text ".Layer_Name" at 577,-858.49 h60
M2 Board Dimensions:
  rectangle: 0,-275 125,-150
  rectangle: 125,-400 500,-275
  lines w7: 0,-275 1000,-275 ; 125,-400 125,-150 ; 250,-400 250,-150 ; 500,-400 500,-150 ; 750,-400 750,-150 ; 0,-400 1000,-400 1000,-150 0,-150 0,-400
  text ".Layer_Name" at 577,-858.49 h60
M3 3D STEP Top:
  text ".Layer_Name" at 577,-858.49 h60
M4 3D STEP Bottom:
  text ".Layer_Name" at 577,-858.49 h60
M5 Assembly Top:
  lines w10: -292,-930.17 6308,-930.17 ; -292,-726.83 6310,-726.83 ; -292,-523.5 -292,-1133.5 3713,-1133.5 6310,-1133.5 6310,-523.5 -291.5,-523.5 -291.5,-1133.5 1284,-1133.5 ; 2173,-1133.5 2173,-523.5 ; 3440,-726.83 3440,-523.5 ; 4280,-726.83 4280,-523.5 ; 4902,-1140 4902,-937.17
  text "COMPONENTS MARKED 'DNP' SHOULD NOT BE POPULATED." at 1153.5,-318.5 h60
  text "ASSEMBLY VARIANT:" at 1153,-434 h60
  text ".VariantName" at 2189,-434 h60
  text "PCB VIEWED FROM TOP SIDE" at -228.5,-655.67 h60
  text "BOARD #:" at 2248,-655.67 h60
  text ".PRJ_Number" at 2793.5,-655.67 h60
  text "REV:" at 3638,-655.67 h60
  text ".PCB_Rev" at 3929.5,-655.67 h60
  text "SVN REV:" at 4476,-655.67 h60
  text ".VersionControl_RevNumber" at 4982,-655.67 h60
  text "TID #:" at 2248,-859 h60
  text ".TID" at 2793.5,-859 h60
  text "PLOT NAME =" at -228.5,-1064.34 h60
  text ".plot_File_Name" at 577,-1064.34 h60
  text "GENERATED    :" at 2250,-1064.34 h60
  text ".Print_Date" at 3119.5,-1064.34 h60
  text ".Print_Time" at 3848.5,-1064.34 h60
  text "TEXAS INSTRUMENTS" at 5113,-1064.34 h60
M6 Assembly Bottom:
  lines w10: -292.5,-727.33 6309.5,-727.33 ; -290.5,-930.67 6309.5,-930.67 ; 1115.5,-1140.5 1115.5,-937.67 ; 1737.5,-727.33 1737.5,-524 ; 2577.5,-727.33 2577.5,-524 ; 3844.5,-1134 3844.5,-524 ; 4733.5,-1134 6309,-1134 6309,-524 -292.5,-524 -292.5,-1134 2304.5,-1134 6309.5,-1134 6309.5,-524
  text "COMPONENTS MARKED 'DNP' SHOULD NOT BE POPULATED." at 6102,-318 h60
  text ".VariantName" at 5058,-434 h60
  text "ASSEMBLY VARIANT:" at 6097,-434 h60
  text ".VersionControl_RevNumber" at 1035.5,-656.17 h60
  text "SVN REV:" at 1541.5,-656.17 h60
  text ".PCB_Rev" at 2088,-656.17 h60
  text "REV:" at 2379.5,-656.17 h60
  text ".PRJ_Number" at 3224,-656.17 h60
  text "BOARD #:" at 3769.5,-656.17 h60
  text "PCB VIEWED FROM BOTTOM SIDE" at 6246,-656.17 h60
  text ".TID" at 3224,-859.5 h60
  text "TID #:" at 3769.5,-859.5 h60
  text "TEXAS INSTRUMENTS" at 904.5,-1064.84 h60
  text ".Print_Time" at 2169,-1064.84 h60
  text ".Print_Date" at 2898,-1064.84 h60
  text "GENERATED    :" at 3767.5,-1064.84 h60
  text ".plot_File_Name" at 5440.5,-1064.84 h60
  text "PLOT NAME =" at 6246,-1064.84 h60
M9 Title Sheet:
  drawing of 57 lines, arcs and shapes, not listed
  text "1" at 739.84,8036.5 h70
  text "2" at 3235.5,8036.5 h70
  text "3" at 5724.84,8036.5 h70
  text "4" at 8231.51,8036.5 h70
  text "5" at 10730.5,8036.5 h70
  text "6" at 13235.5,8036.5 h70
  text "A" at -416.5,6893.5 h70
  text "A" at 14383.5,6893.5 h70
  text "B" at -416.5,4513.5 h70
  text "B" at 14383.5,4513.5 h70
  text "C" at -416.5,2138.5 h70
  text "C" at 14383.5,2138.5 h70
  text "PROJECT TITLE:" at 11343.5,277.5 h45
  text ".PRJ_Title" at 11393.5,144.17 h70
  text "DESIGNED FOR:" at 11343.5,-23.5 h45
  text ".PRJ_Customer" at 11393.5,-163.5 h70
  text "D" at -416.5,-231.5 h70
  text "D" at 14383.5,-231.5 h70
  text "FILE NAME:" at 11343.5,-323.5 h45
  text ".PCB_File_Name_No_Path" at 11393.5,-443.5 h70
  text "Texas Instruments (TI) and/or its licensors do not warrant the accuracy or completeness of this specification" at 6374,-605.34 h45
  text "ENGINEER:" at 11343.5,-613.5 h45
  text "LAYOUT BY:" at 12848.5,-613.5 h45
  text "or any information contained therein. TI and/or its licensors do not warrant that this design will meet" at 6329.01,-718 h45
  text ".PRJ_Engineer" at 11393.5,-768.49 h70
  text ".PCB_Layout" at 12899,-768.49 h70
  text "the specifications, will be suitable for your application or fit for any particular purpose, or will operate in" at 6329.01,-830.67 h45
  text ".Layer_Name" at 577,-858.49 h60
  text "ALTIUM DESIGNER VERSION:" at 12848.5,-923.5 h45
  text "an implementation. TI and/or its licensors do not warrant that the design is production worthy. You should" at 6329.01,-943.33 h45
  text "completely validate and test your design implementation to confirm the system functionality for your application." at 6374,-1056 h45
  text ".print_Scale" at 11393.5,-1056.83 h70
  text ".Application_BuildNumber" at 12899,-1056.83 h70
  text "1" at 739.84,-1263.5 h70
  text "2" at 3235.5,-1263.5 h70
  text "3" at 5724.84,-1263.5 h70
  text "4" at 8231.51,-1263.5 h70
  text "5" at 10730.5,-1263.5 h70
  text "6" at 13235.5,-1263.5 h70
M10 Fab Notes:
  drawing of 189 lines, arcs and shapes, not listed
  text "DESIGN INFORMATION" at 12382.02,6356.17 h60
  text "MIN. TRACK WIDTH:" at 11737.46,6224.05 h60
  text "8" at 12833.7,6224.05 h60
  text "MIL" at 12988.46,6224.05 h60
  text "MIN. CLEARANCE:" at 11737.46,6099.92 h60
  text "0.2" at 12773.7,6099.93 h60
  text "mm" at 12988.46,6099.92 h60
  text "MIN. VIA PAD SIZE:" at 11737.46,5975.8 h60
  text "24" at 12803.71,5975.8 h60
  text "MIL" at 12988.46,5975.8 h60
  text "0.05mm (2MIL)" at 12432.46,5845.9 h60
  text "MINIMUM ANNULAR RING" at 11408.23,5837.67 h60
  text "EXTERNAL" at 13140.46,5837.67 h60
  text "PER" at 11608.23,5727.55 h60
  text "IPC-D-275 CLASS 2 LEVEL C" at 11828.23,5727.54 h60
  text "MIL, HOLES" at 13316.46,5627.07 h60
  text "+/-" at 12924,5618.48 h60
  text "+/-" at 13778,5618.48 h60
  text "REGISTRATION TOLERANCES:" at 11408.23,5617.42 h60
  text "METAL" at 12608,5617.42 h60
  text "5" at 13184.2,5617.42 h60
  text "3" at 14017.2,5617.42 h60
  text "MIL" at 14133.46,5617.42 h60
  text "HOLE SIZE TOLERANCE (UNLESS OTHERWISE SPECIFIED):" at 11408.23,5519.1 h60
  text "+/-" at 13778,5516.23 h60
  text "3" at 14017.2,5515.17 h60
  text "MIL" at 14133.46,5515.17 h60
  text "MATERIAL:" at 11333.46,5377.52 h60
  text "FR-4 High Tg" at 12319.9,5249 h60
  text "X" at 12175.46,5241.01 h60
  text "FR-408" at 11754.46,5236.49 h60
  text "OTHER" at 13242.46,5236.49 h60
  text "62 MIL (1.6mm) +/-10%" at 12074.56,5093.46 h60
  text "X" at 11954.46,5091.01 h60
  text "THICKNESS:" at 11408.23,5085.24 h60
  text "OTHER" at 13359.46,5085.24 h60
  text "TOLERANCE:" at 11408.23,4946.92 h60
  text "X" at 12256.46,4946.92 h60
  text "ANSI IPC-6012 TYPE 3 CLASS 2" at 12434.48,4946.92 h60
  text "OTHER +/-" at 12434.46,4802.73 h60
  text "BOW & TWIST:" at 11408.23,4657.54 h60
  text "X" at 12256.46,4657.54 h60
  text "ANSI IPC-6012 TYPE 3 CLASS 2" at 12434.48,4657.54 h60
  text "OTHER +/-" at 12434.46,4510.85 h60
  text "DRILLING:" at 11333.46,4380.23 h60
  text "NC_DRILL FILES" at 13094.46,4275.04 h60
  text "REFERENCE:" at 11408.23,4271.1 h60
  text "X" at 12065.46,4271.01 h60
  text "AS SHOWN" at 12243.46,4271.1 h60
  text "X" at 12966.46,4271.1 h60
  text "OTHER" at 13392.46,4128.85 h60
  text "PTH COPPER THICKNESS:" at 11407.91,4125.32 h60
  text "X" at 12547.14,4125.32 h60
  text "20-30 um" at 12675.14,4125.32 h60
  text "BOARD FINISH:" at 11333.46,3977.73 h60
  text "SILKSCREEN:" at 11488.68,3867.6 h60
  text "X" at 12446.46,3867.6 h60
  text "TOP" at 12563.46,3867.6 h60
  text "X" at 12956.46,3867.6 h60
  text "BOTTOM" at 13074.46,3867.6 h60
  text "SILKSCREEN COLOR:" at 11488.68,3712.41 h60
  text "X" at 12445.46,3712.41 h60
  text "WHITE" at 12563.46,3712.41 h60
  text "OTHER" at 13074.46,3712.41 h60
  text "X" at 12576.46,3568.96 h60
  text "GREEN" at 12694.46,3568.96 h60
  text "OTHER" at 13312.46,3568.96 h60
  text "SOLDER RESIST COLOR:" at 11488.68,3562.1 h60
  text "X" at 12576.46,3414.71 h60
  text "MATTE" at 12694.46,3414.71 h60
  text "SEMI-GLOSS" at 13312,3414.07 h60
  text "IMMERSION GOLD (ENIG)" at 12394.46,3241.94 h60
  text "ENEPIG" at 13732,3234.72 h60
  text "SURFACE FINISH:" at 11333.46,3233.72 h60
  text "X" at 12216.46,3233.72 h60
  text "IMM. TIN/SILVER OR EQUIV" at 11663,3096.4 h60
  text "OTHER" at 13094.46,3092.47 h60
  text "ARRAY/PANEL:" at 11333.46,2937.09 h60
  text "CUT AND TRIM PER M1 BOARD OUTLINE" at 12394.46,2928.87 h60
  text "N.C. ROUTE" at 12394.46,2792.9 h60
  text "X" at 13082.46,2792.9 h60
  text "V. SCORE" at 13260.46,2792.9 h60
  text "CERTIFICATION:" at 11333.46,2663.77 h60
  text "MATERIALS AND WORKMANSHIP FOR ALL PCBS" at 12058.46,2663.77 h60
  text "TO MEET OR EXCEED THE REQUIREMENTS OF:" at 12058.46,2569.71 h60
  text "X" at 11695.97,2441.08 h60
  text "ANSI IPC-A-600F CLASS ->" at 11823.96,2441.08 h60
  text "X" at 13471.97,2441.08 h60
  text "2" at 13581.96,2441.08 h60
  text "1" at 13266.96,2439.58 h60
  text "3" at 13935.96,2439.58 h60
  text "X" at 12507.97,2293.39 h60
  text "RoHS" at 12635.96,2293.39 h60
  text "OTHER" at 13280.36,2293.39 h60
  text "PER ORDER" at 13677.42,2293.39 h60
  text "ALL BOARDS MUST MEET OR EXCEED UL94-V0 REQUIREMENTS." at 11361,2139.57 h60
  text "PCB MUST BEAR THE UL94V-0 UL REGISTERED MATERIAL ID NUMBER" at 11361,2023.5 h60
  text "ADDITIONAL REQUIREMENTS:" at 11333.46,1854.08 h60
  text "MICROSECTION:" at 11408.23,1746.95 h60
  text "YES" at 12313.96,1746.95 h60
  text "REQUIRED" at 13175.46,1602.62 h60
  text "BARE BOARD ELEC. TEST:" at 11408.23,1599.76 h60
  text "NONE" at 12713.96,1599.76 h60
  text "X" at 13057.46,1599.76 h60
  text "PER ORDER" at 13767.46,1599.76 h60
  text "XX MIL VIAS REQUIRE NON-CONDUCTIVE FILL AND PLANARIZE" at 11576.38,1394.82 h59
  text "XX MIL VIAS REQUIRE CONDUCTIVE FILL AND PLANARIZE" at 11584.38,1290.84 h60
  text "OUTER XX MIL TRACES REQUIRE 50 OHM SINGLE-ENDED IMPEDANCE" at 11583.39,1127.46 h58
  text "LAYER 2 & 3 (INNER LAYERS) XX MIL WIDE, XX MIL SPACE / TRACES REQUIRE 100 OHM DIFFERENTIAL IMPEDANCE" at 11575.39,891.74 h60
  text ".Layer_Name" at 577,-858.49 h60
M11 Gerber Information:
  lines w10: -292,-930.17 6308,-930.17 ; -292,-726.83 6310,-726.83 ; -292,-523.5 -292,-1133.5 3713,-1133.5 6310,-1133.5 6310,-523.5 -291.5,-523.5 -291.5,-1133.5 1284,-1133.5 ; 2173,-1133.5 2173,-523.5 ; 3440,-726.83 3440,-523.5 ; 4280,-726.83 4280,-523.5 ; 4902,-1140 4902,-937.17
  text "ALL ARTWORK VIEWED FROM TOP SIDE" at -228.5,-655.67 h60
  text "BOARD #:" at 2248,-655.67 h60
  text ".PRJ_Number" at 2793.5,-655.67 h60
  text "REV:" at 3638,-655.67 h60
  text ".PCB_Rev" at 3929.5,-655.67 h60
  text "SVN REV:" at 4476,-655.67 h60
  text ".VersionControl_RevNumber" at 4982,-655.67 h60
  text "LAYER NAME =" at -228.5,-858.49 h60
  text "TID #:" at 2248,-859 h60
  text ".TID" at 2793.5,-859 h60
  text "PLOT NAME =" at -228.5,-1064.34 h60
  text ".plot_File_Name" at 577,-1064.34 h60
  text "GENERATED    :" at 2250,-1064.34 h60
  text ".Print_Date" at 3119.5,-1064.34 h60
  text ".Print_Time" at 3848.5,-1064.34 h60
  text "TEXAS INSTRUMENTS" at 5113,-1064.34 h60
M12 Stackup:
  drawing of 191 lines, arcs and shapes, not listed
  text "Layer" at 9797.84,7830 h60
  text "Name" at 10207.76,7830 h60
  text "Material" at 11137.5,7830 h60
  text "Thickness" at 11997.27,7830 h60
  text "Constant" at 12647.1,7830 h60
  text "Board Layer Stack" at 13216.96,7830 h60
  text "1" at 9797.84,7710 h60
  text "Top Overlay" at 10207.76,7710 h60
  text "2" at 9797.84,7590 h60
  text "Top Solder" at 10207.76,7590 h60
  text "Solder Resist" at 11137.5,7590 h60
  text "0.40mil" at 11997.27,7590 h60
  text "3.5" at 12647.1,7590 h60
  text "3" at 9797.84,7470 h60
  text "Top Layer" at 10207.76,7470 h60
  text "Copper" at 11137.5,7470 h60
  text "1.40mil" at 11997.27,7470 h60
  text "4" at 9797.84,7350 h60
  text "Dielectric1" at 10207.76,7350 h60
  text "FR-4" at 11137.5,7350 h60
  text "59.20mil" at 11997.27,7350 h60
  text "4.8" at 12647.1,7350 h60
  text "5" at 9797.84,7230 h60
  text "Bottom Layer" at 10207.76,7230 h60
  text "Copper" at 11137.5,7230 h60
  text "1.40mil" at 11997.27,7230 h60
  text "6" at 9797.84,7110 h60
  text "Bottom Solder" at 10207.76,7110 h60
  text "Solder Resist" at 11137.5,7110 h60
  text "0.40mil" at 11997.27,7110 h60
  text "3.5" at 12647.1,7110 h60
  text "7" at 9797.84,6990 h60
  text "Bottom Overlay" at 10207.76,6990 h60
  text ".Layer_Name" at 577,-858.49 h60
M13 Component Bodies Top:
  text ".Layer_Name" at 577,-858.49 h60
M14 Component Bodies Bottom:
  text ".Layer_Name" at 577,-858.49 h60
M15 Courtyards Top:
  text ".Layer_Name" at 577,-858.49 h60
M16 Courtyards Bottom:
  text ".Layer_Name" at 577,-858.49 h60
Drill Drawing:
  drawing of 187 lines, arcs and shapes, not listed
  text "Symbol" at 97.5,5992.5 h72
  text "Count" at 603.38,5992.5 h72
  text "Hole Size" at 1193.22,5992.5 h72
  text "Plated" at 2342.88,5992.5 h72
  text "Hole Type" at 2848.76,5992.5 h72
  text "Drill Layer Pair" at 3582.56,5992.5 h72
  text "Via/Pad" at 5082.11,5992.5 h72
  text "Pad Shape" at 5671.96,5992.5 h72
  text "Template" at 6417.76,5992.5 h72
  text "Description" at 7397.48,5992.5 h72
  text "Hole Tolerance (+)" at 8251.24,5992.5 h72
  text "Hole Tolerance (-)" at 9584.85,5992.5 h72
  text "1" at 603.38,5842.5 h60
  text "28.00mil (0.711mm)" at 1193.22,5842.5 h60
  text "PTH" at 2342.88,5842.5 h60
  text "Round" at 2848.76,5842.5 h60
  text "Top Layer - Bottom Layer" at 3582.56,5842.5 h60
  text "Pad" at 5082.11,5842.5 h60
  text "Rectangle" at 5671.96,5842.5 h60
  text "s120h71" at 6417.76,5842.5 h60
  text "1" at 603.38,5692.5 h60
  text "28.01mil (0.712mm)" at 1193.22,5692.5 h60
  text "PTH" at 2342.88,5692.5 h60
  text "Round" at 2848.76,5692.5 h60
  text "Top Layer - Bottom Layer" at 3582.56,5692.5 h60
  text "Pad" at 5082.11,5692.5 h60
  text "Rounded" at 5671.96,5692.5 h60
  text "c120h71" at 6417.76,5692.5 h60
  text "1" at 603.38,5542.5 h60
  text "40.00mil (1.016mm)" at 1193.22,5542.5 h60
  text "PTH" at 2342.88,5542.5 h60
  text "Round" at 2848.76,5542.5 h60
  text "Top Layer - Bottom Layer" at 3582.56,5542.5 h60
  text "Pad" at 5082.11,5542.5 h60
  text "Rounded" at 5671.96,5542.5 h60
  text "c203h102" at 6417.76,5542.5 h60
  text "1" at 603.38,5392.5 h60
  text "63.00mil (1.600mm)" at 1193.22,5392.5 h60
  text "PTH" at 2342.88,5392.5 h60
  text "Round" at 2848.76,5392.5 h60
  text "Top Layer - Bottom Layer" at 3582.56,5392.5 h60
  text "Pad" at 5082.11,5392.5 h60
  text "Rounded" at 5671.96,5392.5 h60
  text "c221h160" at 6417.76,5392.5 h60
  text "2" at 603.38,5242.5 h60
  text "41.34mil (1.050mm)" at 1193.22,5242.5 h60
  text "PTH" at 2342.88,5242.5 h60
  text "Round" at 2848.76,5242.5 h60
  text "Top Layer - Bottom Layer" at 3582.56,5242.5 h60
  text "Pad" at 5082.11,5242.5 h60
  text "(Mixed)" at 5671.96,5242.5 h60
  text "(Mixed)" at 6417.76,5242.5 h60
  text "2" at 603.38,5092.5 h60
  text "105.12mil (2.670mm)" at 1193.22,5092.5 h60
  text "PTH" at 2342.88,5092.5 h60
  text "Round" at 2848.76,5092.5 h60
  text "Top Layer - Bottom Layer" at 3582.56,5092.5 h60
  text "Pad" at 5082.11,5092.5 h60
  text "Rounded" at 5671.96,5092.5 h60
  text "c400h267" at 6417.76,5092.5 h60
  text "4" at 603.38,4942.5 h60
  text "25.59mil (0.650mm)" at 1193.22,4942.5 h60
  text "PTH" at 2342.88,4942.5 h60
  text "Round" at 2848.76,4942.5 h60
  text "Top Layer - Bottom Layer" at 3582.56,4942.5 h60
  text "Pad" at 5082.11,4942.5 h60
  text "(Mixed)" at 5671.96,4942.5 h60
  text "(Mixed)" at 6417.76,4942.5 h60
  text "4" at 603.38,4792.5 h60
  text "43.31mil (1.100mm)" at 1193.22,4792.5 h60
  text "PTH" at 2342.88,4792.5 h60
  text "Round" at 2848.76,4792.5 h60
  text "Top Layer - Bottom Layer" at 3582.56,4792.5 h60
  text "Pad" at 5082.11,4792.5 h60
  text "Rounded" at 5671.96,4792.5 h60
  text "c165h110(Tol5-5)" at 6417.76,4792.5 h60
  text "1.97mil (0.050mm)" at 8251.24,4792.5 h60
  text "1.97mil (0.050mm)" at 9584.85,4792.5 h60
  text "A" at 68.41,4782.51 h66.67
  text "4" at 603.38,4642.5 h60
  text "51.18mil (1.300mm)" at 1193.22,4642.5 h60
  text "PTH" at 2342.88,4642.5 h60
  text "Round" at 2848.76,4642.5 h60
  text "Top Layer - Bottom Layer" at 3582.56,4642.5 h60
  text "Pad" at 5082.11,4642.5 h60
  text "(Mixed)" at 5671.96,4642.5 h60
  text "(Mixed)" at 6417.76,4642.5 h60
  text "4" at 603.38,4492.5 h60
  text "125.98mil (3.200mm)" at 1193.22,4492.5 h60
  text "PTH" at 2342.88,4492.5 h60
  text "Round" at 2848.76,4492.5 h60
  text "Top Layer - Bottom Layer" at 3582.56,4492.5 h60
  text "Pad" at 5082.11,4492.5 h60
  text "Rounded" at 5671.96,4492.5 h60
  text "c800h320" at 6417.76,4492.5 h60
  text "6" at 603.38,4342.5 h60
  text "33.47mil (0.850mm)" at 1193.22,4342.5 h60
  text "PTH" at 2342.88,4342.5 h60
  text "Round" at 2848.76,4342.5 h60
  text "Top Layer - Bottom Layer" at 3582.56,4342.5 h60
  text "Pad" at 5082.11,4342.5 h60
  text "(Mixed)" at 5671.96,4342.5 h60
  text "(Mixed)" at 6417.76,4342.5 h60
  text "6" at 603.38,4192.5 h60
  text "62.00mil (1.575mm)" at 1193.22,4192.5 h60
  text "PTH" at 2342.88,4192.5 h60
  text "Round" at 2848.76,4192.5 h60
  text "Top Layer - Bottom Layer" at 3582.56,4192.5 h60
  text "Pad" at 5082.11,4192.5 h60
  text "Rounded" at 5671.96,4192.5 h60
  text "(Mixed)" at 6417.76,4192.5 h60
  text "7" at 603.38,4042.5 h60
  text "55.12mil (1.400mm)" at 1193.22,4042.5 h60
  text "PTH" at 2342.88,4042.5 h60
  text "Round" at 2848.76,4042.5 h60
  text "Top Layer - Bottom Layer" at 3582.56,4042.5 h60
  text "Pad" at 5082.11,4042.5 h60
  text "(Mixed)" at 5671.96,4042.5 h60
  text "(Mixed)" at 6417.76,4042.5 h60
  text "18" at 603.38,3892.5 h60
  text "64.96mil (1.650mm)" at 1193.22,3892.5 h60
  text "PTH" at 2342.88,3892.5 h60
  text "Round" at 2848.76,3892.5 h60
  text "Top Layer - Bottom Layer" at 3582.56,3892.5 h60
  text "Pad" at 5082.11,3892.5 h60
  text "(Mixed)" at 5671.96,3892.5 h60
  text "(Mixed)" at 6417.76,3892.5 h60
  text "111" at 603.38,3742.5 h60
  text "10.00mil (0.254mm)" at 1193.22,3742.5 h60
  text "PTH" at 2342.88,3742.5 h60
  text "Round" at 2848.76,3742.5 h60
  text "Top Layer - Bottom Layer" at 3582.56,3742.5 h60
  text "Via" at 5082.11,3742.5 h60
  text "Rounded" at 5671.96,3742.5 h60
  text "v51h25" at 6417.76,3742.5 h60
  text "172 Total" at 603.38,3592.5 h60
  text ".Layer_Name" at 577,-858.49 h60
M17 Embedded Cavity:
  text ".Layer_Name" at 577,-858.49 h60
M18 Embedded Assembly:
  text ".Layer_Name" at 577,-858.49 h60
M19 Embedded Keepout:
  text ".Layer_Name" at 577,-858.49 h60

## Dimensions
0,-400 to 1000,-400 on M2 Board Dimensions
0,0 to 0,3450 on M2 Board Dimensions
0,0 to 4950,0 on M2 Board Dimensions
